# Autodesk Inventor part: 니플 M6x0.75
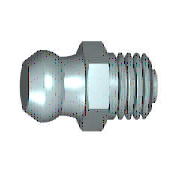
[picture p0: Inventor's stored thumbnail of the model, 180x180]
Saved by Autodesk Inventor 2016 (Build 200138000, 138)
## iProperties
Created: 2012-02
Part Number: 니플 M6x0.75
Material: 강철, 연강
Description: 윤활 니플, 원추 유형 A
Document SubType Name: Modeling
Standard: JIS B 1575
Designer: mduedu
Standards Organization: JIS
Language: ko-KR
Size Designation: MT 6 x 0.75
Categories: <MemberInstance><Categories><Category DisplayName="기타 부품" InternalName="5aa15e00-363f-49f2-933f-16f664388e3f" Mnemonic="OTHER"><Category DisplayName="그리스 부속품" I
Density: 1 g/cm^3
Appearance: 강철
IsCustomPart: 1
Author: mduedu
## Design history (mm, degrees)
sketch "스케치1"
  geometry: L1 (-8.8, 0)-(-8.8, 2.4); L2 (-8.8, 2.4)-(-7.335, 3.202); L3 (-8.8, 0)-(4.7, 0); L4 (4.7, 0)-(4.7, 1.5); L5 (4.7, 1.5)-(4, 1.5); L6 (4, 1.5)-(4, 3); L7 (4, 3)-(0, 3); L8 (-11.5, 0)-(7.4, 0) reference; L9 (0, -1.733)-(0, 10.398) reference; L10 (-3, 3.5)-(0, 3.5); L11 (0, 3.5)-(0, 3); A1 r 3.3 centre (-6.535, 0) between (-4.789, 2.8) and (-7.335, 3.202); A2 r 6 centre (-6.053, 8.665) between (-4.789, 2.8) and (-3, 3.5)
  constraints: 18 end point, 5 perpendicular, 4 point on circle, 2 centre point, 2 parallel, 2 point on line, 1 collinear, 1 vertical
  dimensions: "d0" = 13.5 distance between parallel lines of L1 L4 (= GL); "d1" = 5.6 diameter of A1.start L3 (= KGB2); "d2" = 0.7 distance between parallel lines of L4 L6 (= PHH); "d3" = 3 diameter of L5 L3 (= 0.5 x NND); "d4" = 6 diameter of L7 L3 (= NND); "d5" = 6.6 dimension on A1 L3 (= KR); "d6" = 4.8 diameter of L1.end L3 (= KGB1); "d7" = 6 radius of A2 (= RBN); "d11" = 7 diameter of L10.start L3 (= SW); "d14" = 3 distance of L10.start L10.end (= KOH); "d15" = 4 distance between parallel lines of L6 L11 (= NLG); "d61" = 7.33505 distance from line of L9 L2.end (computed from KGB1, KR, PHH, GL, NLG, VERS); "d62" = 6.53505 distance from line of L9 A1.centre (computed from NLG, GL, PHH, KR, KGB1)
revolve "본체" sketch "스케치1" stored, may be unused: angle "d25" = 90 deg
sketch "스케치2"
  geometry: L1 (2.021, 3.5)-(4.041, 0); L2 (4.041, 0)-(2.021, -3.5); L3 (2.021, -3.5)-(-2.021, -3.5); L4 (-2.021, -3.5)-(-4.041, 0); L5 (-4.041, 0)-(-2.021, 3.5); L6 (-2.021, 3.5)-(2.021, 3.5); C1 r 3.5 at (0, 0) reference; 1 further point
  constraints: 12 end point, 1 coincident, 1 horizontal, 1 tangent, 11 other
extrude "머리" join sketch "스케치2" distance "d17" = 3 (= KOH); taper "d18" = 0 deg
sketch "스케치3"
  geometry: L1 (2.687, 4.041)-(3, 4.041); L2 (3, 4.041)-(3, 3.5); L3 (3, 3.5)-(2.687, 4.041); L4 (0.313, 4.041)-(0, 4.041); L5 (0, 4.041)-(0, 3.5); L6 (0, 3.5)-(0.313, 4.041); L7 (3.6, 0)-(-0.6, 0) reference; L8 (0, 4.041)-(0, 2.021) reference; L9 (0, 4.041)-(3, 4.041) reference; L10 (3, 3.031)-(3, 4.041) reference
  constraints: 12 end point, 4 collinear, 3 perpendicular, 1 horizontal
  dimensions: "d19" = 3.5 distance from line of L5.end L7 (= 0.5 x SW); "d20" = 3.5 distance from line of L2.end L7 (= 0.5 x SW); "d21" = 30 deg angle of L6 L5; "d22" = 30 deg angle of L2 L3
revolve "모따기1" sketch "스케치3" stored, may be unused: angle "d56" = 90 deg
body "Solid1"
fillet "모깎기1" dims "d8" = 0.2 (= RR)
feature "스레드1" dims "d9" = 3.53991 (= NLG - GAL), "d10" = 0
chamfer "모따기2" distance "d23" = 0.46009 (= -0.5 x GD1 + 0.5 x NND); stored, may be unused: angle "d24" = 45 deg, second distance "d59" = 0.46009 (= -0.5 x GD1 + 0.5 x NND)
other parameters: "NLG" = 4 [user parameter; used in 4 equation terms], "GL" = 13.5 [user parameter; used in 3 equation terms], "NND" = 6 [user parameter; used in 4 equation terms], "KGB1" = 4.8 [user parameter; used in 3 equation terms], "KGB2" = 5.6 [user parameter; used in 1 equation term], "VERS" = 0.8 [user parameter; used in 1 equation term], "KR" = 6.6 [user parameter; used in 3 equation terms], "RBN" = 6 [user parameter; used in 1 equation term], "SW" = 7 [user parameter; used in 3 equation terms], "KOH" = 3 [user parameter; used in 2 equation terms], "GAL" = 0.46009 (= 0.61345 x PTC) [user parameter; used in 1 equation term], "FAWI" = 45 deg [user parameter], "PHH" = 0.7 [user parameter; used in 3 equation terms], "GD1" = 5.07983 (= THREADDIA - 1.2269 x PTC) [user parameter; used in 2 equation terms], "RR" = 0.2 [user parameter; used in 1 equation term], "d12" = 0, "d13" = 0, "GUL" = 0.46009 (= 0.61345 x PTC) [user parameter], "TPU" = 13.33333 (computed from PTC) [user parameter], "DULO" = 1.5 [user parameter], "PTC" = 0.75 [user parameter; used in 4 equation terms], "GEL" = 4 [user parameter], "THREADDIA" = 6 [user parameter; used in 1 equation term], "TOA" = 30 deg [user parameter]
